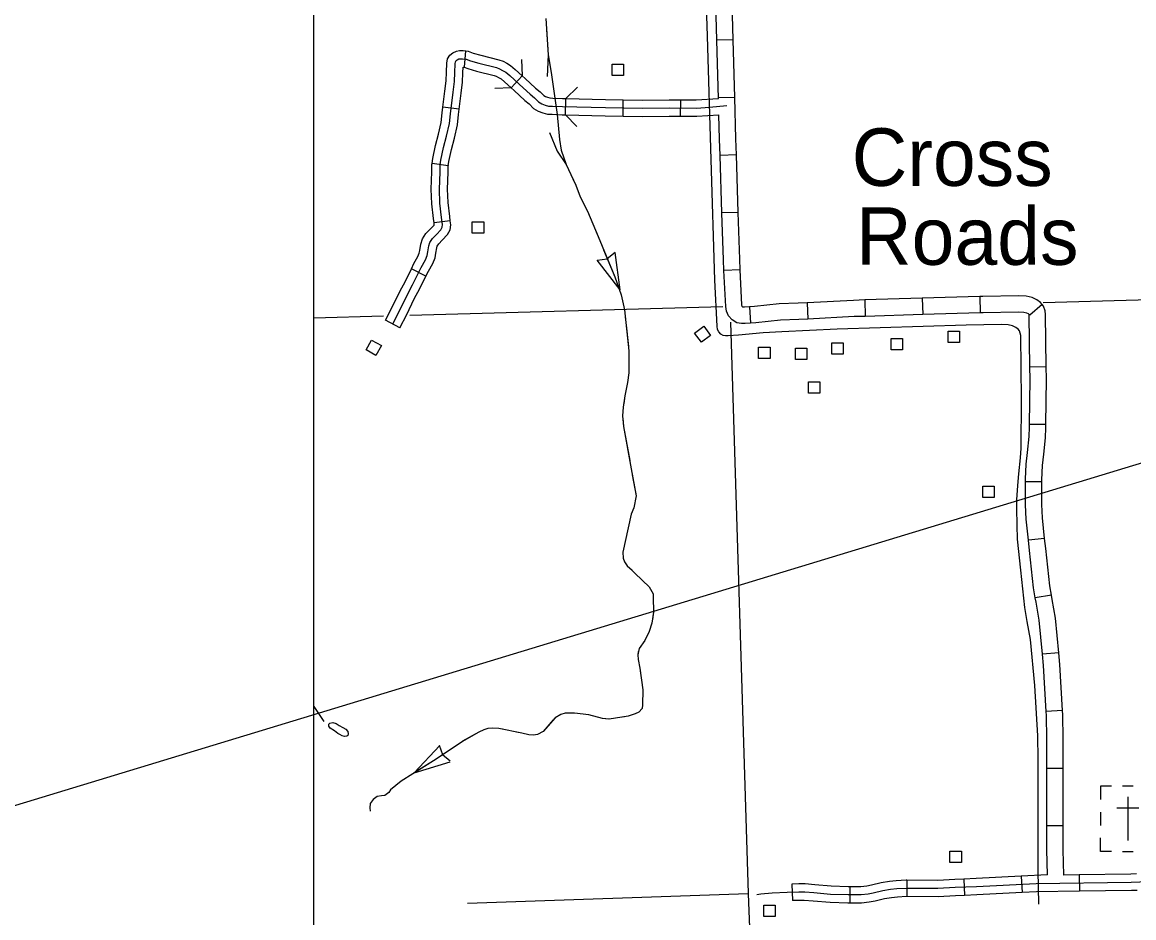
# Model space of a CAD drawing. Extents: x 155 to 3386, y 68 to 2138.
# Drawn here: x 1074 to 1365.4, y 567.8 to 802.6 of the extents above; entities that cross this region are included whole.
import ezdxf

# ---------------------------------------------------------------- set-up
doc = ezdxf.new("R2010")
doc.units = 0
for name, color, linetype in [('2', 7, 'Continuous'), ('Default', 7, 'Continuous'), ('E_No Plot', 7, 'Continuous'), ('Level 24', 7, 'Continuous'), ('Level 32', 7, 'Continuous'), ('Level 35', 7, 'Continuous'), ('Level 38', 7, 'Continuous'), ('Level 4', 7, 'Continuous'), ('Level 43', 7, 'Continuous'), ('Level 47', 7, 'Continuous'), ('Level 5', 7, 'Continuous'), ('Level 56', 7, 'Continuous'), ('Level 57', 7, 'Continuous')]:
    doc.layers.add(name, color=color, linetype=linetype)

msp = doc.modelspace()

# ---------------------------------------------------------------- linework, layer by layer
at = {"layer": '2'}
msp.add_line((1715.85, 793.15), (1068.19, 596), dxfattribs=at)
at = {"layer": 'Default'}
msp.add_lwpolyline([(1150.5, 1308.99), (2342.15, 1308.99), (2342.15, 348.58), (1150.5, 348.58)], close=True, dxfattribs=at)
at = {"layer": 'E_No Plot'}
msp.add_lwpolyline([(1150.5, 1308.99), (2342.15, 1308.99), (2342.15, 348.58), (1150.5, 348.58)], close=True, dxfattribs=at)
msp.add_lwpolyline([(1150.5, 1308.99), (2342.15, 1308.99), (2342.15, 348.58), (1150.5, 348.58)], close=True, dxfattribs=at)
at = {"layer": 'Level 32'}
for p, q in [((1260.37, 798.01), (1256.09, 797.89)), ((1189.93, 790.84), (1190.34, 795.11)), ((1202.2, 785.39), (1205.09, 788.56)), ((1216.4, 778.36), (1216.51, 782.65)), ((1231.5, 778.02), (1231.58, 782.3)), ((1246.61, 778), (1246.63, 782.28)), ((1260.8, 782.93), (1256.51, 782.81)), ((1188.56, 779.85), (1184.3, 780.37)), ((1261.24, 767.86), (1256.95, 767.72)), ((1185.69, 765.02), (1181.44, 765.62)), ((1261.72, 752.78), (1257.43, 752.64)), ((1186.23, 750.54), (1181.98, 750.02)), ((1179.86, 736.04), (1176.02, 737.94)), ((1262.24, 737.74), (1257.96, 737.53)), ((1279.74, 729.09), (1279.96, 724.81)), ((1294.85, 729.8), (1294.98, 725.51)), ((1309.93, 730.24), (1310.06, 725.96)), ((1325.01, 730.69), (1325.14, 726.41)), ((1341.34, 728.66), (1338.15, 725.8)), ((1264.66, 728.01), (1264.95, 723.74)), ((1173.04, 722.54), (1169.23, 724.51)), ((1342.46, 712.25), (1338.17, 712.19)), ((1342.37, 697.12), (1338.09, 697.16)), ((1341.27, 682.1), (1336.98, 682.1)), ((1342.02, 667.28), (1337.76, 666.82)), ((1343.78, 652.44), (1339.56, 651.7)), ((1345.72, 637.33), (1341.46, 636.92)), ((1346.73, 622.2), (1342.45, 621.94)), ((1346.89, 606.99), (1342.6, 606.99)), ((1346.89, 591.9), (1342.6, 591.9)), ((1305.89, 577.65), (1305.86, 573.37)), ((1320.87, 577.97), (1321.04, 573.68)), ((1335.91, 578.69), (1336.13, 574.41)), ((1351.07, 579.05), (1351.13, 574.76)), ((1275.79, 576.6), (1275.97, 572.32)), ((1290.93, 575.97), (1290.93, 571.69))]:
    msp.add_line(p, q, dxfattribs=at)
for points in [[(1340.54, 571.42), (1340.35, 580.24), (1340.35, 586.14), (1340.35, 609.37), (1340.26, 615.54), (1339.48, 628.71), (1338.34, 640.74), (1337.47, 645.54), (1336.83, 649.2), (1335.78, 658.98), (1334.91, 667.12), (1334.78, 670.73), (1334.73, 675.17), (1334.73, 677.36), (1334.96, 681.16), (1335.28, 684.22), (1335.69, 688.43), (1335.83, 690.99), (1335.96, 703.7), (1335.74, 720.48), (1335.64, 721.12), (1335.46, 721.72), (1335.05, 722.17), (1334.5, 722.59), (1333.63, 723), (1332.45, 723.27), (1330.71, 723.36), (1321.48, 723.18), (1287.61, 722.17), (1273.12, 721.44), (1268.23, 721.21), (1261.79, 720.57), (1259.05, 720.39), (1258.36, 720.39), (1257.72, 720.48), (1257.13, 720.85), (1256.58, 721.44), (1256.3, 722.08), (1256.17, 722.91), (1255.57, 735.02), (1254.57, 766.62), (1253.65, 798.99), (1252.97, 820.26)], [(1256.09, 797.89), (1255.9, 804.32), (1255.63, 812.96)], [(1260.37, 798.01), (1260.19, 804.45), (1259.91, 813.1)], [(1256.52, 782.64), (1256.09, 797.89)], [(1260.8, 782.93), (1260.37, 798.01)], [(1171.13, 723.53), (1172.92, 726.96), (1174.89, 731.09), (1176.36, 733.79), (1178.6, 738.33), (1179.7, 740.3), (1180.16, 741.45), (1180.34, 742.41), (1180.57, 743.97), (1180.89, 744.88), (1181.53, 745.89), (1182.59, 746.95), (1183.73, 748.18), (1184.1, 748.87), (1184.19, 749.56), (1183.96, 751.44), (1183.5, 755.17), (1183.37, 758.88), (1183.55, 763.33), (1183.55, 765.2), (1183.73, 766.49), (1184.47, 769.79), (1185.24, 772.74), (1185.98, 776.04), (1186.25, 778.65), (1186.94, 784.28), (1187.31, 787.08), (1187.4, 789.46), (1187.49, 791.71), (1187.58, 792.26), (1187.76, 792.58), (1188.04, 792.81), (1188.45, 792.99), (1188.82, 793.04), (1189.46, 793.04), (1190.42, 792.95), (1191.52, 792.49), (1193.67, 791.89), (1198.34, 790.75), (1199.17, 790.42), (1199.95, 790.01), (1200.77, 789.51), (1201.83, 788.64), (1204.39, 786.3), (1207.19, 783.73), (1208.34, 782.77), (1209.39, 781.72), (1210.21, 781.21), (1211.08, 780.89), (1212, 780.66), (1213.05, 780.62), (1215.62, 780.53), (1226.89, 780.25), (1236.55, 780.07), (1243.61, 780.16), (1250.76, 780.11), (1254.19, 780.34), (1258.71, 780.8)], [(1184.3, 780.37), (1184.81, 784.55), (1185.17, 787.26), (1185.26, 789.55), (1185.35, 791.93), (1185.53, 792.99), (1186.09, 793.98), (1186.89, 794.64), (1187.87, 795.08), (1188.68, 795.18), (1189.56, 795.18), (1190.34, 795.11)], [(1190.34, 795.11), (1190.95, 795.05), (1192.22, 794.52), (1194.21, 793.97), (1198.99, 792.79), (1200.06, 792.38), (1201.01, 791.88), (1202.02, 791.26), (1203.23, 790.26), (1205.09, 788.56)], [(1188.56, 779.85), (1189.06, 784.02), (1189.44, 786.9), (1189.54, 789.38), (1189.6, 790.87), (1189.93, 790.84)], [(1189.89, 790.84), (1190.82, 790.46), (1193.13, 789.82), (1197.7, 788.7), (1198.28, 788.47), (1198.89, 788.15), (1199.53, 787.76), (1200.42, 787.02), (1202.2, 785.39)], [(1205.09, 788.56), (1205.84, 787.88), (1208.6, 785.34), (1209.78, 784.35), (1210.72, 783.41), (1211.15, 783.15), (1211.72, 782.94), (1212.31, 782.79), (1213.14, 782.76), (1215.68, 782.67), (1216.51, 782.65)], [(1202.2, 785.39), (1202.95, 784.72), (1205.77, 782.12), (1206.89, 781.19), (1208.05, 780.02), (1209.28, 779.27), (1210.45, 778.84), (1211.69, 778.53), (1212.97, 778.48), (1215.56, 778.38), (1216.4, 778.36)], [(1216.51, 782.65), (1226.94, 782.39), (1231.58, 782.3)], [(1231.58, 782.3), (1236.56, 782.21), (1243.6, 782.3), (1246.63, 782.28)], [(1246.63, 782.28), (1250.69, 782.26), (1256.52, 782.64)], [(1261.24, 767.86), (1261.1, 772.08), (1260.8, 782.93)], [(1181.44, 765.62), (1181.62, 766.87), (1182.38, 770.29), (1183.16, 773.24), (1183.86, 776.38), (1184.12, 778.89), (1184.3, 780.37)], [(1185.69, 765.02), (1185.84, 766.1), (1186.55, 769.28), (1187.33, 772.23), (1188.09, 775.69), (1188.38, 778.41), (1188.56, 779.85)], [(1216.4, 778.36), (1226.84, 778.11), (1231.5, 778.02)], [(1231.5, 778.02), (1236.55, 777.92), (1243.62, 778.02), (1246.61, 778)], [(1246.61, 778), (1250.82, 777.97), (1256.64, 778.36)], [(1256.95, 767.72), (1256.82, 771.95), (1256.64, 778.36)], [(1257.43, 752.64), (1256.95, 767.72)], [(1261.72, 752.78), (1261.24, 767.86)], [(1181.98, 750.02), (1181.83, 751.18), (1181.37, 755), (1181.22, 758.88), (1181.41, 763.37), (1181.41, 765.36), (1181.44, 765.62)], [(1186.23, 750.54), (1186.09, 751.7), (1185.64, 755.34), (1185.51, 758.88), (1185.69, 763.28), (1185.69, 765.05), (1185.69, 765.02)], [(1257.96, 737.53), (1257.82, 740.33), (1257.43, 752.64)], [(1262.24, 737.74), (1262.11, 740.5), (1261.72, 752.78)], [(1176.02, 737.94), (1176.7, 739.33), (1177.76, 741.22), (1178.09, 742.05), (1178.23, 742.76), (1178.48, 744.48), (1178.95, 745.82), (1179.85, 747.24), (1181.04, 748.43), (1181.97, 749.43), (1182.03, 749.54), (1182.03, 749.57), (1181.98, 750.02)], [(1179.86, 736.04), (1180.5, 737.33), (1181.64, 739.38), (1182.23, 740.84), (1182.46, 742.05), (1182.66, 743.45), (1182.83, 743.94), (1183.22, 744.54), (1184.13, 745.46), (1185.49, 746.93), (1186.17, 748.2), (1186.35, 749.55), (1186.23, 750.54)], [(1169.23, 724.51), (1171, 727.92), (1172.98, 732.06), (1174.45, 734.78), (1176.02, 737.94)], [(1264.95, 723.74), (1263.51, 723.64), (1262.6, 723.64), (1261.37, 723.82), (1260.14, 724.57), (1259.15, 725.65), (1258.62, 726.87), (1258.42, 728.07), (1257.96, 737.53)], [(1264.66, 728.01), (1263.37, 727.93), (1262.91, 727.93), (1262.88, 727.93), (1262.8, 728.02), (1262.77, 728.08), (1262.69, 728.53), (1262.24, 737.74)], [(1173.04, 722.54), (1174.84, 726.01), (1176.8, 730.11), (1178.26, 732.81), (1179.86, 736.04)], [(1279.74, 729.09), (1277.41, 728.98), (1272.47, 728.75), (1266, 728.1), (1264.66, 728.01)], [(1294.85, 729.8), (1291.92, 729.71), (1279.74, 729.09)], [(1309.93, 730.24), (1294.85, 729.8)], [(1325.01, 730.69), (1309.93, 730.24)], [(1341.34, 728.66), (1340.9, 729.16), (1340.01, 729.82), (1338.73, 730.43), (1337.14, 730.8), (1335.14, 730.9), (1325.82, 730.72), (1325.01, 730.69)], [(1342.46, 712.25), (1342.27, 726.04), (1342.13, 726.99), (1341.76, 728.19), (1341.34, 728.66)], [(1294.98, 725.51), (1292.09, 725.43), (1279.96, 724.81)], [(1310.06, 725.96), (1294.98, 725.51)], [(1325.14, 726.41), (1310.06, 725.96)], [(1338.15, 725.8), (1337.99, 725.98), (1337.78, 726.14), (1337.32, 726.36), (1336.54, 726.54), (1335.07, 726.61), (1325.92, 726.43), (1325.14, 726.41)], [(1338.17, 712.19), (1337.99, 725.71), (1337.94, 726.03), (1338.15, 725.8)], [(1279.96, 724.81), (1277.62, 724.7), (1272.78, 724.47), (1266.36, 723.83), (1264.95, 723.74)], [(1338.09, 697.16), (1338.21, 709.09), (1338.17, 712.19)], [(1342.37, 697.12), (1342.5, 709.1), (1342.46, 712.25)], [(1336.98, 682.1), (1336.98, 682.82), (1337.22, 686.73), (1337.54, 689.83), (1337.95, 693.98), (1338.08, 696.45), (1338.09, 697.16)], [(1341.27, 682.1), (1341.27, 682.69), (1341.49, 686.38), (1341.8, 689.4), (1342.22, 693.66), (1342.36, 696.31), (1342.37, 697.12)], [(1337.76, 666.82), (1337.17, 672.36), (1337.03, 676.07), (1336.98, 680.55), (1336.98, 682.1)], [(1342.02, 667.28), (1341.44, 672.67), (1341.31, 676.18), (1341.27, 680.57), (1341.27, 682.1)], [(1343.78, 652.44), (1343.35, 654.89), (1342.31, 664.6), (1342.02, 667.28)], [(1339.56, 651.7), (1339.1, 654.29), (1338.04, 664.15), (1337.76, 666.82)], [(1341.46, 636.92), (1340.61, 645.84), (1339.76, 650.56), (1339.56, 651.7)], [(1345.72, 637.33), (1344.86, 646.42), (1343.98, 651.31), (1343.78, 652.44)], [(1342.45, 621.94), (1341.74, 633.94), (1341.46, 636.92)], [(1346.73, 622.2), (1346.01, 634.27), (1345.72, 637.33)], [(1342.6, 606.99), (1342.6, 614.75), (1342.51, 620.86), (1342.45, 621.94)], [(1346.89, 606.99), (1346.89, 614.78), (1346.8, 621.01), (1346.73, 622.2)], [(1342.6, 591.9), (1342.6, 606.99)], [(1346.89, 591.9), (1346.89, 606.99)], [(1342.74, 579.04), (1342.6, 585.61), (1342.6, 591.53), (1342.6, 591.9)], [(1347.03, 578.99), (1346.89, 585.66), (1346.89, 591.53), (1346.89, 591.9)], [(1412.03, 578.87), (1364.7, 577.1), (1339.84, 576.75), (1324.17, 575.95), (1318.56, 575.73), (1314.05, 575.47), (1305.8, 575.51), (1303.24, 575.38), (1301.6, 575.2), (1299.62, 574.89), (1297.1, 574.27), (1295.73, 574.01), (1293.92, 573.83), (1290.48, 573.83), (1285.93, 573.96), (1281.56, 574.32), (1279.13, 574.54), (1277.63, 574.54), (1274.54, 574.41), (1270.59, 574.27), (1267.64, 574.01), (1266.62, 573.83)], [(1305.89, 577.65), (1305.75, 577.65), (1303.07, 577.51), (1301.32, 577.33), (1299.2, 576.99), (1296.64, 576.37), (1295.42, 576.13), (1293.82, 575.97), (1290.93, 575.97)], [(1320.87, 577.97), (1318.45, 577.87), (1314, 577.61), (1305.89, 577.65)], [(1335.91, 578.69), (1324.07, 578.09), (1320.87, 577.97)], [(1342.74, 579.04), (1335.91, 578.69)], [(1351.07, 579.05), (1347.03, 578.99)], [(1366.1, 579.3), (1364.64, 579.24), (1351.07, 579.05)], [(1290.93, 575.97), (1290.51, 575.97), (1286.05, 576.1), (1281.74, 576.45), (1279.23, 576.68), (1277.58, 576.68), (1275.79, 576.6)], [(1336.13, 574.41), (1324.26, 573.81), (1321.04, 573.68)], [(1351.13, 574.76), (1339.91, 574.6), (1336.13, 574.41)], [(1366.26, 575.01), (1364.75, 574.96), (1351.13, 574.76)], [(1290.93, 571.69), (1290.45, 571.69), (1285.81, 571.82), (1281.37, 572.18), (1279.03, 572.39), (1277.67, 572.39), (1275.97, 572.32)], [(1305.86, 573.37), (1305.85, 573.37), (1303.41, 573.24), (1301.88, 573.08), (1300.04, 572.79), (1297.56, 572.18), (1296.04, 571.88), (1294.02, 571.69), (1290.93, 571.69)], [(1321.04, 573.68), (1318.66, 573.59), (1314.11, 573.32), (1305.86, 573.37)]]:
    msp.add_lwpolyline(points, dxfattribs=at)
at = {"layer": 'Level 35'}
for points in [[(1155.87, 616.85), (1154.73, 617.55), (1154.36, 618.03), (1154.36, 618.58), (1154.62, 618.87), (1155.46, 619.02), (1156.34, 618.76), (1157.08, 618.21), (1158.1, 617.73), (1158.87, 617.25), (1159.39, 616.63), (1159.46, 616.08), (1159.39, 615.64), (1159.13, 615.42), (1158.54, 615.38), (1157.88, 615.49), (1157.26, 615.86), (1156.75, 616.15), (1155.87, 616.85)], [(1170.59, 601.4), (1170.08, 600.71), (1169.11, 599.88), (1168.17, 599.77), (1167.08, 599.59), (1166, 598.8), (1165.24, 597.75), (1165.17, 596.67), (1165.19, 595.73)]]:
    msp.add_lwpolyline(points, dxfattribs=at)
at = {"layer": 'Level 38'}
for points in [[(1204.9, 792.88), (1205.1, 788.6)], [(1202.21, 785.43), (1197.93, 785.24)], [(1216.51, 782.65), (1219.61, 785.6)], [(1219.36, 775.26), (1216.4, 778.36)]]:
    msp.add_lwpolyline(points, dxfattribs=at)
at = {"layer": 'Level 4'}
msp.add_lwpolyline([(1259.7, 723.99), (1264.31, 574.19), (1264.4, 571.85), (1267.19, 502.05)], dxfattribs=at)
at = {"layer": 'Level 43'}
for p, q in [((1224.77, 740.28), (1227.36, 740.62)), ((1230.72, 732.49), (1224.77, 740.28)), ((1229.46, 742.21), (1227.39, 740.63)), ((1230.72, 732.49), (1229.46, 742.21)), ((1176.8, 605.83), (1183.45, 613.03)), ((1183.35, 613.06), (1184.2, 610.59)), ((1186.18, 608.85), (1184.22, 610.56)), ((1176.8, 605.83), (1186.16, 608.74))]:
    msp.add_line(p, q, dxfattribs=at)
for points in [[(1211.23, 803.6), (1211.92, 794.11), (1212.64, 789.45), (1214.23, 778.42), (1214.88, 771.89), (1215.27, 769.12), (1216.57, 765.3), (1219.13, 759.88), (1220.28, 756.85), (1222.16, 753.09), (1225.41, 745.4), (1229.34, 735.83), (1231.05, 731.15), (1231.85, 727.18), (1233.04, 716.49), (1233.04, 710.67), (1232.64, 708.14), (1231.99, 704.68), (1231.56, 701.72), (1231.38, 699.44), (1231.59, 696.66), (1233.65, 685.54), (1234.91, 678.46), (1234.3, 675.28), (1233.65, 673.65), (1231.48, 663.72), (1231.56, 662.09), (1231.88, 661.12), (1232.6, 660.14), (1236.5, 656.35), (1238.34, 654.62), (1239.43, 652.78), (1239.43, 651.87), (1239.5, 647.99), (1239.03, 645.03), (1238.34, 642.87), (1237.26, 640.55), (1235.74, 638.42), (1235.53, 637.63), (1235.38, 636.73), (1235.49, 635.57), (1235.92, 633.29), (1236.72, 627.58), (1236.65, 623.61)], [(1211.44, 800.75), (1211.92, 794.11), (1211.61, 788.37)], [(1212.23, 773.75), (1214.21, 768.84), (1216.57, 765.3), (1218.95, 760.26)], [(1220.33, 756.75), (1222.16, 753.09), (1224.97, 746.44)], [(1226.41, 742.95), (1229.34, 735.83), (1229.53, 735.32)], [(1232.05, 725.32), (1232.29, 723.19)], [(1232.29, 723.19), (1232.92, 717.57)], [(1233.04, 713.81), (1233.04, 710.67), (1232.64, 708.14), (1231.99, 704.68), (1231.69, 702.61)], [(1231.42, 698.85), (1231.59, 696.66), (1233.25, 687.7)], [(1233.93, 683.99), (1234.91, 678.46), (1234.3, 675.28), (1233.65, 673.65), (1233.5, 672.96)], [(1232.7, 669.28), (1231.48, 663.72), (1231.56, 662.09), (1231.88, 661.12), (1232.6, 660.14), (1233.86, 658.92)], [(1236.57, 656.29), (1238.34, 654.62), (1239.43, 652.78), (1239.43, 651.87), (1239.5, 647.99), (1239.19, 646.06)], [(1238.15, 642.45), (1237.26, 640.55), (1235.74, 638.42), (1235.53, 637.63), (1235.51, 637.51)], [(1235.51, 637.51), (1235.38, 636.73), (1235.49, 635.57), (1235.92, 633.29), (1236.11, 631.92)], [(1236.63, 628.18), (1236.72, 627.58), (1236.65, 623.61), (1236.5, 622.67), (1235.67, 621.73), (1234.66, 621.26), (1232.82, 620.68), (1231.35, 620.45)], [(1236.65, 623.61), (1236.5, 622.67), (1235.67, 621.73), (1234.66, 621.26), (1232.82, 620.68), (1227.87, 619.89), (1226.14, 620.11), (1222.53, 621.01), (1218.81, 621.44), (1216.36, 621.44), (1215.17, 621.15), (1213.72, 620.25), (1210.58, 616.67), (1209.1, 615.88), (1208.02, 615.7), (1206.83, 615.77), (1204.99, 616.2), (1198.96, 617.47), (1197.33, 617.51), (1196.11, 617.43), (1195.02, 617.14), (1193.69, 616.53), (1189.39, 614.07), (1182.53, 609.45), (1173.33, 603.64), (1170.59, 601.4)], [(1227.63, 619.92), (1226.14, 620.11), (1222.53, 621.01), (1218.81, 621.44), (1216.46, 621.44)], [(1213.23, 619.69), (1210.58, 616.67), (1209.1, 615.88), (1208.02, 615.7), (1206.83, 615.77), (1204.99, 616.2), (1203.58, 616.5)], [(1199.89, 617.27), (1198.96, 617.47), (1197.33, 617.51), (1196.11, 617.43), (1195.02, 617.14), (1193.69, 616.53), (1189.42, 614.09)], [(1186.29, 611.98), (1182.53, 609.45), (1176.8, 605.83)], [(1173.61, 603.82), (1173.33, 603.64), (1170.59, 601.4)]]:
    msp.add_lwpolyline(points, dxfattribs=at)
at = {"layer": 'Level 47'}
msp.add_lwpolyline([(1150.5, 623.18), (1153.08, 619.3)], dxfattribs=at)
at = {"layer": 'Level 5'}
for points in [[(1341.66, 729.13), (1413.11, 731.14)], [(1150.5, 725.11), (1168.71, 725.62)], [(1175.64, 725.81), (1257.71, 728.13)], [(1190.7, 571.69), (1264.31, 574.19)]]:
    msp.add_lwpolyline(points, dxfattribs=at)
at = {"layer": 'Level 56'}
for points in [[(1228.67, 788.64), (1228.67, 791.61), (1231.65, 791.61), (1231.65, 788.64)], [(1192, 747.3), (1192, 750.28), (1194.99, 750.28), (1194.99, 747.3)], [(1250.27, 721.12), (1252.66, 722.9), (1254.44, 720.51), (1252.05, 718.73)], [(1301.78, 716.74), (1301.78, 719.71), (1304.76, 719.71), (1304.76, 716.74)], [(1316.75, 718.69), (1316.75, 721.66), (1319.73, 721.66), (1319.73, 718.69)], [(1164.14, 716.7), (1165.58, 719.3), (1168.19, 717.86), (1166.75, 715.26)], [(1267.06, 714.48), (1267.06, 717.45), (1270.04, 717.45), (1270.04, 714.48)], [(1276.74, 714.2), (1276.74, 717.17), (1279.72, 717.17), (1279.72, 714.2)], [(1286.26, 715.61), (1286.26, 718.58), (1289.25, 718.58), (1289.25, 715.61)], [(1280.13, 705.4), (1280.13, 708.37), (1283.11, 708.37), (1283.11, 705.4)], [(1325.81, 678.04), (1325.81, 681.01), (1328.8, 681.01), (1328.8, 678.04)], [(1317.21, 582.31), (1317.21, 585.28), (1320.19, 585.28), (1320.19, 582.31)], [(1268.41, 568.19), (1268.41, 571.16), (1271.4, 571.16), (1271.4, 568.19)]]:
    msp.add_lwpolyline(points, close=True, dxfattribs=at)
at = {"layer": 'Level 57'}
for p, q in [((1365.26, 602.36), (1362.4, 602.36)), ((1363.81, 599.5), (1363.81, 588.08)), ((1356.67, 595.55), (1356.67, 591.98)), ((1360.96, 596.65), (1366.7, 596.65)), ((1363.81, 593.79), (1363.81, 593.79)), ((1363.81, 593.79), (1363.81, 593.79)), ((1362.4, 585.22), (1365.26, 585.22))]:
    msp.add_line(p, q, dxfattribs=at)
for points in [[(1359.53, 602.36), (1356.67, 602.36), (1356.67, 598.79)], [(1359.53, 585.22), (1356.67, 585.22), (1356.67, 588.79)]]:
    msp.add_lwpolyline(points, dxfattribs=at)

# ---------------------------------------------------------------- texts
at = {"layer": 'Level 24'}
for s, p in [('Cross', (1291.45, 759.72)), ('Roads', (1292.58, 739.02))]:
    msp.add_text(s, height=15.086, dxfattribs=at).set_placement(p)

doc.saveas('drawing.dxf')
